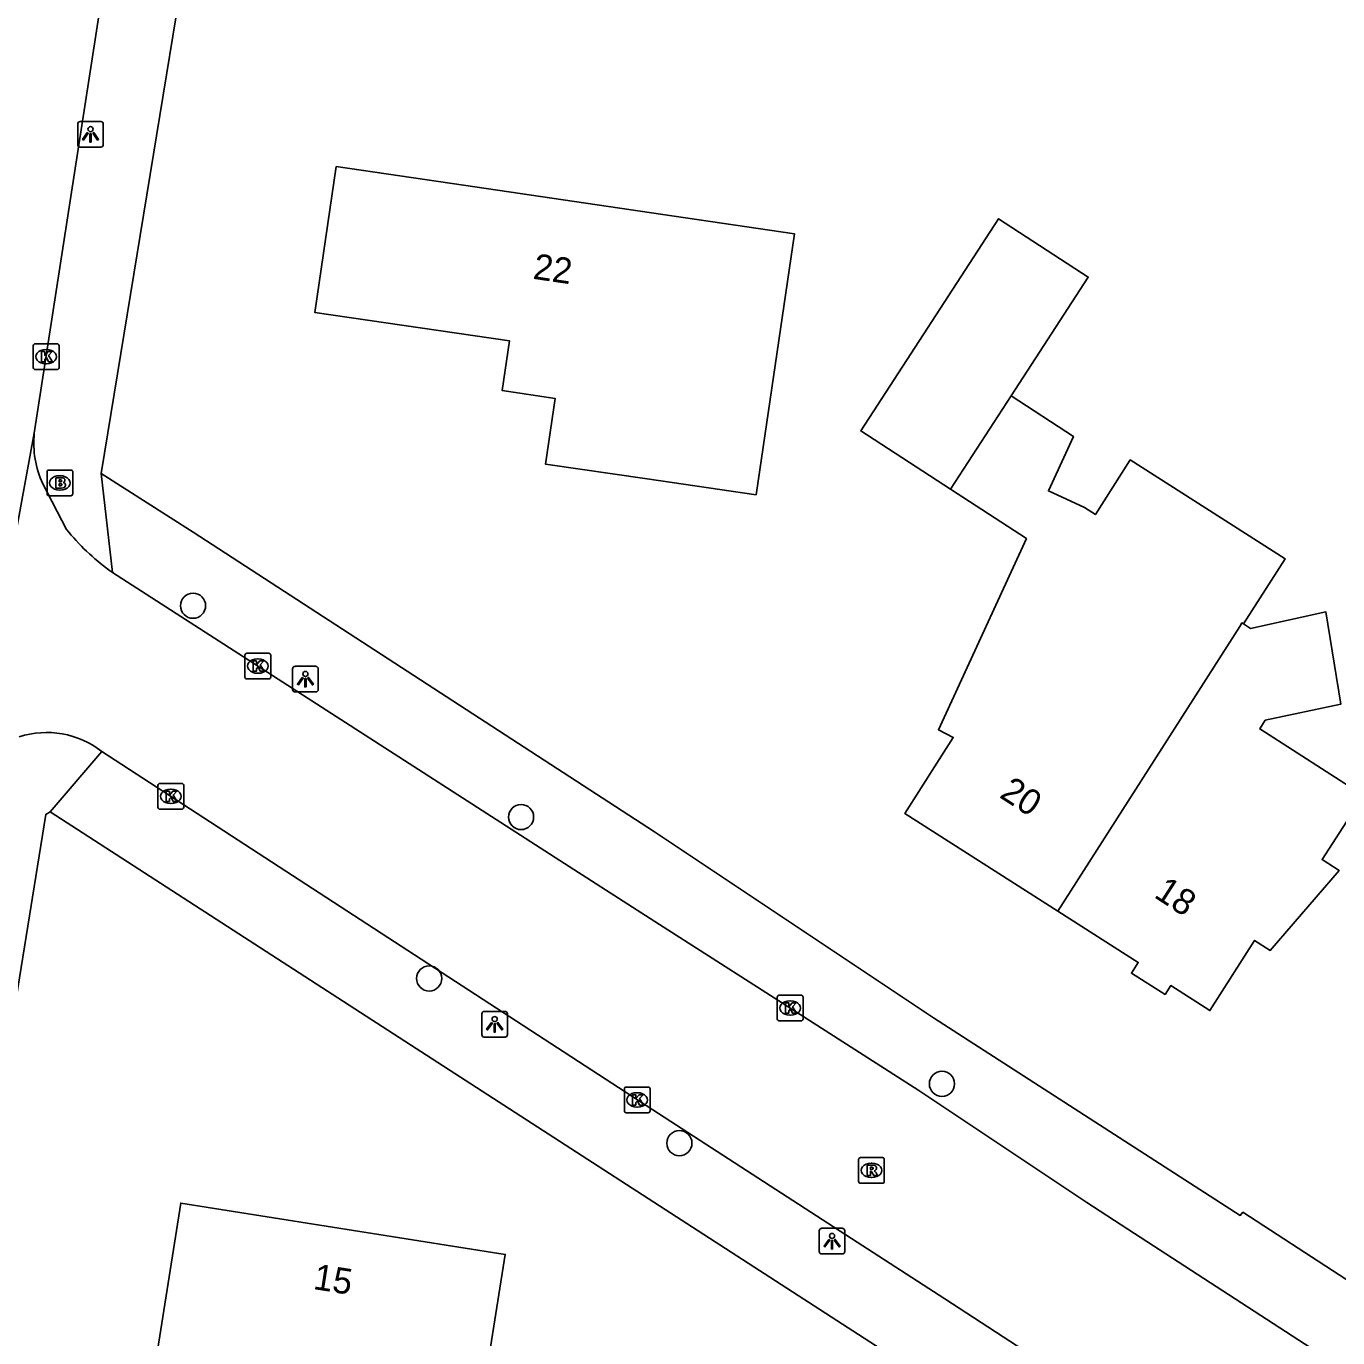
# Model space of a CAD drawing. Extents: x 161141 to 161601, y 381708 to 382245.
# Drawn here: x 161275.4 to 161326.4, y 381968.7 to 382019.7 of the extents above; entities that cross this region are included whole.
import ezdxf

# ---------------------------------------------------------------- set-up
doc = ezdxf.new("R2010")
doc.units = 0
for name, color, linetype in [('IMGEO_Boom', 7, 'Continuous'), ('IMGEO_Brandkraan', 7, 'Continuous'), ('IMGEO_Kolk', 7, 'Continuous'), ('IMGEO_Lichtpunt', 7, 'Continuous'), ('IMGEO_Pand', 7, 'Continuous'), ('IMGEO_Pand_nummerreeks', 7, 'Continuous'), ('IMGEO_Rijbaan_lokaal_open', 7, 'Continuous'), ('IMGEO_Rioolput', 7, 'Continuous'), ('IMGEO_Voetpad_open', 7, 'Continuous')]:
    doc.layers.add(name, color=color, linetype=linetype)

msp = doc.modelspace()

# ---------------------------------------------------------------- linework, layer by layer
at = {"layer": 'IMGEO_Boom'}
for centre in [(161281.874, 381997.141), (161294.634, 381988.923), (161291.06, 381982.646), (161311.007, 381978.547), (161300.792, 381976.24)]:
    msp.add_circle(centre, 0.489, dxfattribs=at)
at = {"layer": 'IMGEO_Brandkraan'}
for p, q in [((161276.192, 382001.493), (161276.192, 382002.345)), ((161276.267, 382002.419), (161277.119, 382002.419)), ((161277.193, 382002.345), (161277.193, 382001.493)), ((161276.68, 382002.199), (161276.705, 382002.199)), ((161277.119, 382001.419), (161276.267, 382001.419)), ((161276.703, 382001.639), (161276.678, 382001.639))]:
    msp.add_line(p, q, dxfattribs=at)
for points in [[(161276.192, 382001.493), (161276.192, 382002.345)], [(161276.267, 382002.419), (161277.119, 382002.419)], [(161277.193, 382002.345), (161277.193, 382001.493)], [(161276.54, 382002.119), (161276.54, 382001.719), (161276.753, 382001.719)], [(161276.771, 382002.119), (161276.54, 382002.119)], [(161276.719, 382002.038), (161276.665, 382002.038), (161276.665, 382001.962)], [(161276.665, 382001.962), (161276.718, 382001.962)], [(161276.727, 382001.886), (161276.665, 382001.886), (161276.665, 382001.805)], [(161276.665, 382001.805), (161276.727, 382001.805)], [(161277.119, 382001.419), (161276.267, 382001.419)]]:
    msp.add_lwpolyline(points, dxfattribs=at)
for centre, radius, start, end in [((161276.269, 382002.343), 0.0765, 91.552, 178.448), ((161276.269, 382002.343), 0.0765, 91.552, 178.448), ((161277.117, 382002.343), 0.0765, 1.552, 88.448), ((161277.117, 382002.343), 0.0765, 1.552, 88.448), ((161276.72, 382002), 0.0379, 267.8285, 90.9355), ((161276.728, 382001.845), 0.0404, 269.8759, 90.5077), ((161276.759, 382001.97), 0.251, 268.6676, 293.5347), ((161276.775, 382001.974), 0.145, 59.4692, 91.5367), ((161276.8, 382002.021), 0.0922, 285.5137, 58.1501), ((161276.805, 382001.829), 0.105, 301.3115, 78.989), ((161276.269, 382001.495), 0.0765, 181.552, 268.448), ((161276.269, 382001.495), 0.0765, 181.552, 268.448), ((161277.117, 382001.495), 0.0765, 271.552, 358.448), ((161277.117, 382001.495), 0.0765, 271.552, 358.448)]:
    msp.add_arc(centre, radius, start, end, dxfattribs=at)
for centre, major_axis, ratio, start_param, end_param in [((161276.679, 382001.919), (-0.387, 0.002), 0.722429, 4.712389, 7.853982), ((161276.704, 382001.919), (-0.39, 0.002), 0.717154, 1.570796, 4.712389)]:
    msp.add_ellipse(centre, major_axis=major_axis, ratio=ratio, start_param=start_param, end_param=end_param, dxfattribs=at)
at = {"layer": 'IMGEO_Kolk'}
for p, q in [((161275.733, 382007.328), (161276.585, 382007.328)), ((161275.658, 382006.402), (161275.658, 382007.254)), ((161276.146, 382007.108), (161276.171, 382007.108)), ((161276.659, 382007.254), (161276.659, 382006.402)), ((161276.585, 382006.328), (161275.733, 382006.328)), ((161276.169, 382006.548), (161276.144, 382006.548)), ((161283.893, 381994.369), (161283.893, 381995.221)), ((161283.968, 381995.295), (161284.82, 381995.295)), ((161284.894, 381995.221), (161284.894, 381994.369)), ((161284.381, 381995.075), (161284.406, 381995.075)), ((161284.82, 381994.295), (161283.968, 381994.295)), ((161284.404, 381994.515), (161284.379, 381994.515)), ((161280.507, 381989.303), (161280.507, 381990.155)), ((161280.582, 381990.229), (161281.434, 381990.229)), ((161280.995, 381990.009), (161281.02, 381990.009)), ((161281.508, 381990.155), (161281.508, 381989.303)), ((161281.434, 381989.229), (161280.582, 381989.229)), ((161281.018, 381989.449), (161280.993, 381989.449)), ((161304.601, 381981.069), (161304.601, 381981.921)), ((161304.676, 381981.995), (161305.528, 381981.995)), ((161305.602, 381981.921), (161305.602, 381981.069)), ((161305.089, 381981.775), (161305.114, 381981.775)), ((161305.528, 381980.995), (161304.676, 381980.995)), ((161305.112, 381981.215), (161305.087, 381981.215)), ((161298.651, 381977.496), (161298.651, 381978.348)), ((161298.726, 381978.422), (161299.578, 381978.422)), ((161299.652, 381978.348), (161299.652, 381977.496)), ((161299.139, 381978.202), (161299.164, 381978.202)), ((161299.578, 381977.422), (161298.726, 381977.422)), ((161299.162, 381977.642), (161299.137, 381977.642))]:
    msp.add_line(p, q, dxfattribs=at)
for points in [[(161275.733, 382007.328), (161276.585, 382007.328)], [(161275.658, 382006.402), (161275.658, 382007.254)], [(161275.979, 382007.028), (161276.102, 382007.028), (161276.102, 382006.877), (161276.232, 382007.028), (161276.396, 382007.028), (161276.25, 382006.877), (161276.403, 382006.628), (161276.251, 382006.628), (161276.166, 382006.792), (161276.102, 382006.725), (161276.102, 382006.628), (161275.979, 382006.628), (161275.979, 382007.028)], [(161276.659, 382007.254), (161276.659, 382006.402)], [(161276.585, 382006.328), (161275.733, 382006.328)], [(161283.893, 381994.369), (161283.893, 381995.221)], [(161283.968, 381995.295), (161284.82, 381995.295)], [(161284.894, 381995.221), (161284.894, 381994.369)], [(161284.214, 381994.995), (161284.337, 381994.995), (161284.337, 381994.844), (161284.467, 381994.995), (161284.631, 381994.995), (161284.485, 381994.844), (161284.638, 381994.595), (161284.486, 381994.595), (161284.401, 381994.759), (161284.337, 381994.692), (161284.337, 381994.595), (161284.214, 381994.595), (161284.214, 381994.995)], [(161284.82, 381994.295), (161283.968, 381994.295)], [(161280.507, 381989.303), (161280.507, 381990.155)], [(161280.582, 381990.229), (161281.434, 381990.229)], [(161281.508, 381990.155), (161281.508, 381989.303)], [(161280.828, 381989.929), (161280.951, 381989.929), (161280.951, 381989.778), (161281.081, 381989.929), (161281.245, 381989.929), (161281.099, 381989.778), (161281.252, 381989.529), (161281.1, 381989.529), (161281.015, 381989.693), (161280.951, 381989.626), (161280.951, 381989.529), (161280.828, 381989.529), (161280.828, 381989.929)], [(161281.434, 381989.229), (161280.582, 381989.229)], [(161304.601, 381981.069), (161304.601, 381981.921)], [(161304.676, 381981.995), (161305.528, 381981.995)], [(161305.602, 381981.921), (161305.602, 381981.069)], [(161304.922, 381981.695), (161305.045, 381981.695), (161305.045, 381981.544), (161305.175, 381981.695), (161305.339, 381981.695), (161305.193, 381981.544), (161305.346, 381981.295), (161305.194, 381981.295), (161305.109, 381981.459), (161305.045, 381981.392), (161305.045, 381981.295), (161304.922, 381981.295), (161304.922, 381981.695)], [(161305.528, 381980.995), (161304.676, 381980.995)], [(161298.651, 381977.496), (161298.651, 381978.348)], [(161298.726, 381978.422), (161299.578, 381978.422)], [(161299.652, 381978.348), (161299.652, 381977.496)], [(161298.972, 381978.122), (161299.095, 381978.122), (161299.095, 381977.971), (161299.225, 381978.122), (161299.389, 381978.122), (161299.243, 381977.971), (161299.396, 381977.722), (161299.244, 381977.722), (161299.159, 381977.886), (161299.095, 381977.819), (161299.095, 381977.722), (161298.972, 381977.722), (161298.972, 381978.122)], [(161299.578, 381977.422), (161298.726, 381977.422)]]:
    msp.add_lwpolyline(points, dxfattribs=at)
for centre, start, end in [((161275.735, 382007.252), 91.552, 178.448), ((161275.735, 382007.252), 91.552, 178.448), ((161276.583, 382007.252), 1.552, 88.448), ((161276.583, 382007.252), 1.552, 88.448), ((161275.735, 382006.404), 181.552, 268.448), ((161275.735, 382006.404), 181.552, 268.448), ((161276.583, 382006.404), 271.552, 358.448), ((161276.583, 382006.404), 271.552, 358.448), ((161283.97, 381995.219), 91.552, 178.448), ((161283.97, 381995.219), 91.552, 178.448), ((161284.818, 381995.219), 1.552, 88.448), ((161284.818, 381995.219), 1.552, 88.448), ((161283.97, 381994.371), 181.552, 268.448), ((161283.97, 381994.371), 181.552, 268.448), ((161284.818, 381994.371), 271.552, 358.448), ((161284.818, 381994.371), 271.552, 358.448), ((161280.584, 381990.153), 91.552, 178.448), ((161280.584, 381990.153), 91.552, 178.448), ((161281.432, 381990.153), 1.552, 88.448), ((161281.432, 381990.153), 1.552, 88.448), ((161280.584, 381989.305), 181.552, 268.448), ((161280.584, 381989.305), 181.552, 268.448), ((161281.432, 381989.305), 271.552, 358.448), ((161281.432, 381989.305), 271.552, 358.448), ((161304.678, 381981.919), 91.552, 178.448), ((161304.678, 381981.919), 91.552, 178.448), ((161305.526, 381981.919), 1.552, 88.448), ((161305.526, 381981.919), 1.552, 88.448), ((161304.678, 381981.071), 181.552, 268.448), ((161304.678, 381981.071), 181.552, 268.448), ((161305.526, 381981.071), 271.552, 358.448), ((161305.526, 381981.071), 271.552, 358.448), ((161298.728, 381978.346), 91.552, 178.448), ((161298.728, 381978.346), 91.552, 178.448), ((161299.576, 381978.346), 1.552, 88.448), ((161299.576, 381978.346), 1.552, 88.448), ((161298.728, 381977.498), 181.552, 268.448), ((161298.728, 381977.498), 181.552, 268.448), ((161299.576, 381977.498), 271.552, 358.448), ((161299.576, 381977.498), 271.552, 358.448)]:
    msp.add_arc(centre, 0.0765, start, end, dxfattribs=at)
for centre, major_axis, ratio, start_param, end_param in [((161276.145, 382006.828), (-0.387, 0.002), 0.722429, 4.712389, 7.853982), ((161276.17, 382006.828), (-0.39, 0.002), 0.717154, 1.570796, 4.712389), ((161284.38, 381994.795), (-0.387, 0.002), 0.722429, 4.712389, 7.853982), ((161284.405, 381994.795), (-0.39, 0.002), 0.717154, 1.570796, 4.712389), ((161280.994, 381989.729), (-0.387, 0.002), 0.722429, 4.712389, 7.853982), ((161281.019, 381989.729), (-0.39, 0.002), 0.717154, 1.570796, 4.712389), ((161305.088, 381981.495), (-0.387, 0.002), 0.722429, 4.712389, 7.853982), ((161305.113, 381981.495), (-0.39, 0.002), 0.717154, 1.570796, 4.712389), ((161299.138, 381977.922), (-0.387, 0.002), 0.722429, 4.712389, 7.853982), ((161299.163, 381977.922), (-0.39, 0.002), 0.717154, 1.570796, 4.712389)]:
    msp.add_ellipse(centre, major_axis=major_axis, ratio=ratio, start_param=start_param, end_param=end_param, dxfattribs=at)
at = {"layer": 'IMGEO_Lichtpunt'}
for p, q in [((161277.386, 382015.88), (161277.386, 382015.073)), ((161277.386, 382015.88), (161277.386, 382015.073)), ((161278.288, 382015.975), (161277.48, 382015.975)), ((161278.288, 382015.975), (161277.48, 382015.975)), ((161278.382, 382015.073), (161278.382, 382015.88)), ((161278.382, 382015.073), (161278.382, 382015.88)), ((161277.48, 382014.979), (161278.288, 382014.979)), ((161277.48, 382014.979), (161278.288, 382014.979)), ((161285.745, 381994.69), (161285.745, 381993.883)), ((161285.745, 381994.69), (161285.745, 381993.883)), ((161286.647, 381994.785), (161285.839, 381994.785)), ((161286.647, 381994.785), (161285.839, 381994.785)), ((161286.741, 381993.883), (161286.741, 381994.69)), ((161286.741, 381993.883), (161286.741, 381994.69)), ((161285.839, 381993.789), (161286.647, 381993.789)), ((161285.839, 381993.789), (161286.647, 381993.789)), ((161294.009, 381981.363), (161293.201, 381981.363)), ((161294.009, 381981.363), (161293.201, 381981.363)), ((161293.107, 381981.268), (161293.107, 381980.461)), ((161293.107, 381981.268), (161293.107, 381980.461)), ((161294.103, 381980.461), (161294.103, 381981.268)), ((161294.103, 381980.461), (161294.103, 381981.268)), ((161293.201, 381980.367), (161294.009, 381980.367)), ((161293.201, 381980.367), (161294.009, 381980.367)), ((161306.231, 381972.832), (161306.231, 381972.025)), ((161306.231, 381972.832), (161306.231, 381972.025)), ((161307.133, 381972.927), (161306.325, 381972.927)), ((161307.133, 381972.927), (161306.325, 381972.927)), ((161307.227, 381972.025), (161307.227, 381972.832)), ((161307.227, 381972.025), (161307.227, 381972.832)), ((161306.325, 381971.931), (161307.133, 381971.931)), ((161306.325, 381971.931), (161307.133, 381971.931))]:
    msp.add_line(p, q, dxfattribs=at)
for points in [[(161277.76, 382015.544), (161277.799, 382015.516), (161277.611, 382015.254), (161277.573, 382015.281), (161277.76, 382015.544)], [(161277.862, 382015.496), (161277.909, 382015.496), (161277.909, 382015.174), (161277.862, 382015.174), (161277.862, 382015.496)], [(161277.972, 382015.516), (161278.01, 382015.543), (161278.197, 382015.281), (161278.158, 382015.253), (161277.972, 382015.516)], [(161286.119, 381994.354), (161286.158, 381994.326), (161285.97, 381994.064), (161285.932, 381994.091), (161286.119, 381994.354)], [(161286.221, 381994.306), (161286.268, 381994.306), (161286.268, 381993.984), (161286.221, 381993.984), (161286.221, 381994.306)], [(161286.331, 381994.326), (161286.369, 381994.353), (161286.556, 381994.091), (161286.517, 381994.063), (161286.331, 381994.326)], [(161293.481, 381980.932), (161293.52, 381980.904), (161293.332, 381980.642), (161293.294, 381980.669), (161293.481, 381980.932)], [(161293.583, 381980.884), (161293.63, 381980.884), (161293.63, 381980.562), (161293.583, 381980.562), (161293.583, 381980.884)], [(161293.693, 381980.904), (161293.731, 381980.931), (161293.918, 381980.669), (161293.879, 381980.641), (161293.693, 381980.904)], [(161306.605, 381972.496), (161306.644, 381972.468), (161306.456, 381972.206), (161306.418, 381972.233), (161306.605, 381972.496)], [(161306.707, 381972.448), (161306.754, 381972.448), (161306.754, 381972.126), (161306.707, 381972.126), (161306.707, 381972.448)], [(161306.817, 381972.468), (161306.855, 381972.495), (161307.042, 381972.233), (161307.003, 381972.205), (161306.817, 381972.468)]]:
    msp.add_lwpolyline(points, dxfattribs=at)
for centre in [(161277.885, 382015.678), (161286.244, 381994.488), (161293.606, 381981.066), (161306.73, 381972.63)]:
    msp.add_circle(centre, 0.0994, dxfattribs=at)
for centre, start, end in [((161277.48, 382015.88), 90, 180), ((161277.48, 382015.88), 90, 180), ((161278.288, 382015.88), 0, 90), ((161278.288, 382015.88), 0, 90), ((161277.48, 382015.073), 180, 270), ((161277.48, 382015.073), 180, 270), ((161278.288, 382015.073), 270, 0), ((161278.288, 382015.073), 270, 360), ((161285.839, 381994.69), 90, 180), ((161285.839, 381994.69), 90, 180), ((161286.647, 381994.69), 0, 90), ((161286.647, 381994.69), 0, 90), ((161285.839, 381993.883), 180, 270), ((161285.839, 381993.883), 180, 270), ((161286.647, 381993.883), 270, 0), ((161286.647, 381993.883), 270, 360), ((161293.201, 381981.268), 90, 180), ((161293.201, 381981.268), 90, 180), ((161294.009, 381981.268), 0, 90), ((161294.009, 381981.268), 0, 90), ((161293.201, 381980.461), 180, 270), ((161293.201, 381980.461), 180, 270), ((161294.009, 381980.461), 270, 0), ((161294.009, 381980.461), 270, 360), ((161306.325, 381972.832), 90, 180), ((161306.325, 381972.832), 90, 180), ((161307.133, 381972.832), 0, 90), ((161307.133, 381972.832), 0, 90), ((161306.325, 381972.025), 180, 270), ((161306.325, 381972.025), 180, 270), ((161307.133, 381972.025), 270, 0), ((161307.133, 381972.025), 270, 360)]:
    msp.add_arc(centre, 0.0946, start, end, dxfattribs=at)
at = {"layer": 'IMGEO_Pand'}
for points in [[(161303.775, 382001.453), (161299.54, 382002.074), (161295.582, 382002.654), (161295.956, 382005.206), (161293.903, 382005.507), (161294.186, 382007.443), (161286.609, 382008.553), (161287.441, 382014.225), (161292.389, 382013.5), (161301.029, 382012.233), (161305.264, 382011.612), (161303.775, 382001.453)], [(161311.336, 382001.672), (161307.849, 382003.938), (161313.212, 382012.191), (161316.699, 382009.925), (161313.698, 382005.307)], [(161311.336, 382001.672), (161313.698, 382005.307)], [(161313.698, 382005.307), (161316.118, 382003.727), (161315.145, 382001.608), (161316.552, 382000.963), (161316.978, 382000.69), (161318.331, 382002.81), (161324.352, 381998.967), (161322.733, 381996.437)], [(161315.516, 381985.262), (161309.559, 381989.066), (161311.443, 381992.018), (161310.875, 381992.313), (161314.292, 381999.751), (161311.336, 382001.672)], [(161322.733, 381996.437), (161323.014, 381996.257), (161325.944, 381996.899), (161326.519, 381993.307), (161323.584, 381992.685), (161323.366, 381992.35), (161327.411, 381989.759), (161325.791, 381987.268), (161326.455, 381986.845), (161323.779, 381983.735), (161323.17, 381984.124), (161321.429, 381981.396), (161319.905, 381982.369), (161319.684, 381982.022), (161318.379, 381982.855), (161318.642, 381983.266), (161315.516, 381985.262)], [(161315.516, 381985.262), (161322.589, 381996.335), (161322.677, 381996.473), (161322.733, 381996.437)], [(161291.811, 381958.087), (161279.219, 381960.153), (161281.395, 381973.911), (161294.018, 381971.914), (161293.408, 381968.055), (161299.194, 381967.02), (161298.451, 381962.239), (161292.636, 381963.173), (161291.811, 381958.087)]]:
    msp.add_lwpolyline(points, dxfattribs=at)
at = {"layer": 'IMGEO_Rijbaan_lokaal_open'}
for points in [[(161275.698, 382003.858), (161279.948, 382031.313)], [(161275.698, 382003.858), (161273.208, 381990.334)], [(161277.041, 382000), (161276.948, 382000.112), (161276.03, 382001.882)], [(161325.373, 381968.263), (161318.237, 381972.89), (161316.637, 381973.927), (161310.106, 381978.294), (161303.837, 381982.304), (161300.012, 381984.75), (161296.327, 381987.12), (161278.737, 381998.431)], [(161278.323, 381991.478), (161299.753, 381977.533), (161307.482, 381972.536), (161311.114, 381970.18), (161315.062, 381967.62), (161315.173, 381967.548), (161318.89, 381965.138), (161327.462, 381959.489), (161330.866, 381957.332), (161337.714, 381952.958), (161346.638, 381947.161), (161350.625, 381944.584), (161357.825, 381939.931), (161366.222, 381934.52), (161372.037, 381930.857), (161375.083, 381928.811)]]:
    msp.add_lwpolyline(points, dxfattribs=at)
for centre, radius, start, end in [((161279.437, 382003.47), 3.759, 174.081, 204.9941), ((161283.935, 382005.751), 8.977, 219.834, 234.6211), ((161276.181, 381988.718), 3.494, 52.1814, 107.884)]:
    msp.add_arc(centre, radius, start, end, dxfattribs=at)
at = {"layer": 'IMGEO_Rioolput'}
for p, q in [((161307.763, 381974.755), (161307.763, 381975.607)), ((161307.838, 381975.681), (161308.69, 381975.681)), ((161308.251, 381975.461), (161308.276, 381975.461)), ((161308.764, 381975.607), (161308.764, 381974.755)), ((161308.69, 381974.681), (161307.838, 381974.681)), ((161308.274, 381974.901), (161308.249, 381974.901))]:
    msp.add_line(p, q, dxfattribs=at)
for points in [[(161307.763, 381974.755), (161307.763, 381975.607)], [(161307.838, 381975.681), (161308.69, 381975.681)], [(161308.352, 381975.379), (161308.1, 381975.381), (161308.1, 381974.981)], [(161308.278, 381975.3), (161308.224, 381975.3), (161308.224, 381975.219)], [(161308.224, 381975.219), (161308.276, 381975.219)], [(161308.764, 381975.607), (161308.764, 381974.755)], [(161308.69, 381974.681), (161307.838, 381974.681)], [(161308.1, 381974.981), (161308.224, 381974.981), (161308.224, 381975.143), (161308.235, 381975.143)], [(161308.282, 381975.114), (161308.353, 381974.981), (161308.493, 381974.981), (161308.428, 381975.107)]]:
    msp.add_lwpolyline(points, dxfattribs=at)
for centre, radius, start, end in [((161307.84, 381975.605), 0.0765, 91.552, 178.448), ((161307.84, 381975.605), 0.0765, 91.552, 178.448), ((161308.26, 381975.408), 0.19, 274.7715, 282.9687), ((161308.284, 381975.204), 0.0964, 77.0061, 93.1865), ((161308.298, 381975.261), 0.0378, 276.6634, 79.6772), ((161308.351, 381975.269), 0.109, 350.3612, 89.416), ((161308.349, 381975.269), 0.112, 277.5842, 350.9817), ((161308.688, 381975.605), 0.0765, 1.552, 88.448), ((161308.688, 381975.605), 0.0765, 1.552, 88.448), ((161307.84, 381974.757), 0.0765, 181.552, 268.448), ((161307.84, 381974.757), 0.0765, 181.552, 268.448), ((161308.234, 381975.09), 0.0533, 26.0293, 88.6989), ((161308.333, 381975.054), 0.108, 29.5134, 73.7905), ((161308.688, 381974.757), 0.0765, 271.552, 358.448), ((161308.688, 381974.757), 0.0765, 271.552, 358.448)]:
    msp.add_arc(centre, radius, start, end, dxfattribs=at)
for centre, major_axis, ratio, start_param, end_param in [((161308.25, 381975.181), (-0.387, 0.002), 0.722429, 4.712389, 7.853982), ((161308.275, 381975.181), (-0.39, 0.002), 0.717154, 1.570796, 4.712389)]:
    msp.add_ellipse(centre, major_axis=major_axis, ratio=ratio, start_param=start_param, end_param=end_param, dxfattribs=at)
at = {"layer": 'IMGEO_Voetpad_open'}
for points in [[(161301.893, 382073.339), (161290.838, 382055.877), (161287.538, 382048.363), (161285.187, 382041.077), (161283.628, 382034.817), (161278.294, 382002.287)], [(161278.294, 382002.287), (161281.877, 382000), (161299.823, 381988.353), (161310.674, 381981.109), (161322.611, 381973.432), (161322.712, 381973.551), (161378.924, 381936.994), (161385.641, 381932.206), (161392.817, 381926.552), (161429.313, 381896.994)], [(161278.737, 381998.431), (161278.294, 382002.287)], [(161278.323, 381991.478), (161276.309, 381989.126)], [(161276.309, 381989.126), (161276.14, 381989.025), (161267.873, 381937.797), (161267.435, 381933.784), (161267.467, 381929.855), (161267.871, 381925.589), (161268.634, 381921.624), (161269.796, 381917.444), (161271.533, 381912.948), (161272.783, 381910.378), (161277.045, 381903.774)], [(161370.462, 381928.258), (161276.309, 381989.126)]]:
    msp.add_lwpolyline(points, dxfattribs=at)

# ---------------------------------------------------------------- texts
at = {"layer": 'IMGEO_Pand_nummerreeks'}
for s, rotation, p in [('22', 351.6657, (161295.065, 382009.861)), ('20', 327.1294, (161313.203, 381989.712)), ('18', 327.1294, (161319.214, 381985.827)), ('15', 351.0078, (161286.515, 381970.57))]:
    msp.add_text(s, height=1, rotation=rotation, dxfattribs=at).set_placement(p)

doc.saveas('drawing.dxf')
